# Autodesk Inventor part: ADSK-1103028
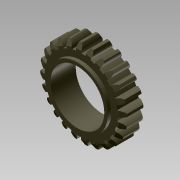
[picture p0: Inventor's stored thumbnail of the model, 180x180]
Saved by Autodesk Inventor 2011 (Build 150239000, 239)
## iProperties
Shininess: 41.0
Length Units: 11272
Angle Units: 11279
Time Units: 11290
Mass Units: 11286
Length Display Precision: 4
Angle Display Precision: 2
Compacted: True
Created: 2000-06
Part Number: ADSK-1103028
Document SubType Name: Modeling
Description: 24 TOOTH CLUTCH GEAR
Mass: 6.16542 g
Surface Area: 11.6587 cm^2
Volume: 0.786406 cm^3
Density: 7.84 g/cm^3
Material: Steel, High Strength Low Alloy
Density: 0.0
Volumn: 0.0
Area: 0.0
PropertySet Name: Model Information
Control State: 0
Master: False
Checked Out: False
Author: Autodesk, Inc.
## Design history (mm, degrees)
node "Extrusion1" dims "d2" = 5.08 (= Thickness), "d3" = 0
  sketch "Sketch2"
    geometry: C1 r 8.607 at (0, 0); 1 further point
    constraints: 1 centre point, 1 coincident
    dimensions: "d0" = 17.21326 diameter of C1 (= RD)
node "Extrusion2" dims "d17" = 6.35, "d18" = 0
  sketch "Sketch3"
    geometry: L1 (0, 0)-(0, 27.478); L2 (0, 9.525)-(-7.278, 9.525); L3 (0, 9.525)-(-4.075, 8.471); L4 (0.054, 9.221)-(0.051, 8.606); L5 (-0.675, 10.297)-(-0.563, 8.588); C1 r 8.607 at (0, 0) reference; A1 r 10.319 centre (0, 0) between (-0.371, 10.312) and (-0.675, 10.297); A2 r 9.525 centre (0, 0) between (0, 9.525) and (-0.623, 9.505); A3 r 9.222 centre (0, 0) between (-2.309, 8.928) and (0.054, 9.221); A4 r 8.607 centre (0, 0) between (0.051, 8.606) and (-0.563, 8.588); A5 r 2.381 centre (-2.309, 8.928) between (0.054, 9.221) and (-0.371, 10.312)
    constraints: 10 end point, 10 point on circle, 5 centre point, 5 point on line, 1 concentric, 1 perpendicular, 1 tangent, 1 vertical
    dimensions: "d4" = 20.6375 diameter of A1 (= OD); "d5" = 19.05 diameter of A2 (= PD); "d6" = 18.44321 diameter of A3 (= BC); "d7" = 17.21326 diameter of A4 (= RD); "d8" = 14.5 deg angle of L2 L3 (= AN); "d9" = 4.7625 diameter of A5 (= 0.25 x PD); "d10" = 0.62309 distance of L2.start A2.end (= 0.5 x CT)
node "Mirror1"
node "Extrusion4" dims "d25" = 0.8636, "d26" = 0
  sketch "Sketch5"
    geometry: C1 r 7.144 at (0, 0); A1 r 10.319 centre (0, 0) between (-4.834, -9.116) and (-4.29, -9.385) reference
    constraints: 1 centre point, 1 coincident
    dimensions: "d30" = 14.2875 diameter of C1
node "Extrusion5" dims "d28" = 5.08, "d29" = 0
  sketch "Sketch6"
    geometry: C1 r 7.144 at (0, 0) reference; C2 r 6.35 at (0, 0)
    constraints: 1 centre point, 1 coincident
    dimensions: "d27" = 12.7 diameter of C2
workaxis "Work Axis2"
workplane "Work Plane2"
  workpoint "Work Point1"
node "Revolution1" dims "d34" = 90 deg
  sketch "Sketch7"
    geometry: L1 (-10.314, -0.864)-(-9.049, -0.864); L2 (-9.049, -0.864)-(-10.319, -1.499); L3 (-10.319, -5.944)-(-9.049, -5.944); L4 (-9.049, -5.944)-(-10.319, -5.309); L5 (0, 1.189)-(0, -7.132) reference; L6 (-10.319, -0.864)-(-10.319, -5.944) reference; L7 (-10.314, -0.864)-(-10.319, -0.864)
    constraints: 10 end point, 2 perpendicular, 2 point on line, 1 equal length, 1 parallel
    dimensions: "d31" = 0.635 distance of L1.start L2.end; "d33" = 0.635 distance from line of L4.end L3 (= d31); "d35" = 1.27 distance from line of L6 L1.end (= 2 x d31)
body "Solid1"
node "Circular Pattern1" dims "d19" = 240 (= NM), "d21" = 360 deg
other parameters: "PD" = 19.05 [user parameter; used in 2 equation terms], "ADD" = 0.79375 [user parameter], "DED" = 0.91837 [user parameter], "CL" = 0.12462 [user parameter], "OD" = 20.6375 [user parameter; used in 1 equation term], "RD" = 17.21326 [user parameter; used in 2 equation terms], "BC" = 18.44321 [user parameter; used in 1 equation term], "CP" = 2.49364 [user parameter], "CT" = 1.24619 [user parameter; used in 1 equation term], "AN" = 14.5 deg [user parameter; used in 1 equation term], "d1" = 36.26326 [user parameter], "Thickness" = 5.08 [user parameter; used in 1 equation term], "d11" = 39.6875 [user parameter], "d12" = 38.1 [user parameter], "d13" = 36.88643 [user parameter], "d14" = 36.26326 [user parameter], "d15" = 14.5 deg [user parameter], "d16" = 1.24619 [user parameter]
